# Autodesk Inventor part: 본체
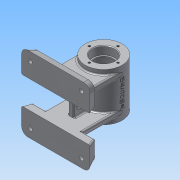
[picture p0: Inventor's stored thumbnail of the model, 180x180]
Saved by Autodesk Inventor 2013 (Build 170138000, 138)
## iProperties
Created: 2016-07
Part Number: 본체
Material: 알루미늄 6061
Document SubType Name: Modeling
Designer: Administrator
Density: 2.71 g/cm^3
Mass: 504.06 g
Surface Area: 540.608 cm^2
Volume: 186 cm^3
Author: Administrator
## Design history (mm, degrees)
sketch "스케치1"
  geometry: C1 r 27 at (0, 0); 1 further point
  constraints: 1 centre point, 1 coincident
  dimensions: "d0" = 54 diameter of C1
extrude "돌출1" new body sketch "스케치1" distance "d1" = 35; taper "d2" = 0 deg
sketch "스케치2"
  geometry: C1 r 27 at (0, 0) reference; C2 r 16 at (0, 0)
  constraints: 1 centre point, 1 coincident
  dimensions: "d3" = 32 diameter of C2
extrude "돌출2" cut sketch "스케치2" distance "d4" = 12; taper "d5" = 0 deg
chamfer "모따기1" distance "d6" = 1; stored, may be unused: second distance "d7" = 2, angle "d8" = 45 deg
fillet "모깎기1" dims "d9" = 0.3
sketch "스케치3"
  geometry: C1 r 15.7 at (0, 0) reference; C2 r 14 at (0, 0)
  constraints: 1 centre point, 1 coincident
  dimensions: "d10" = 28 diameter of C2
extrude "돌출3" cut sketch "스케치3" distance "d11" = 2; taper "d12" = 0 deg
sketch "스케치4"
  geometry: C1 r 27 at (0, 0) reference; C2 r 22 at (0, 0)
  constraints: 1 centre point, 1 coincident
  dimensions: "d13" = 44 diameter of C2
extrude "돌출4" cut sketch "스케치4" distance "d14" = 21; taper "d15" = 0 deg
fillet "모깎기2" dims "d16" = 3
sketch "스케치5"
  geometry: C1 r 27 at (0, 0) reference; 1 further point
  constraints: 1 vertical alignment
  dimensions: "d17" = 21 distance of C1.centre point (0, 21)
hole "구멍1" sketch "스케치5" at (0, 21) diameter "d18" = 3.242; stored, may be unused: countersink angle "d22" = 90 deg, drill point angle "d24" = 118 deg; dims "d19" = 8, "d20" = 4, "d21" = 2, "d23" = 10
node "작업 평면1"
sketch "스케치6"
  geometry: L1 (27, 35)-(-27, 35) reference; C1 r 5 at (0, 13); 2 further points
  constraints: 1 centre point, 1 midpoint, 1 vertical alignment
  dimensions: "d29" = 10 diameter of C1; "d30" = 22 distance from line of C1.centre L1
extrude "돌출5" join sketch "스케치6" stored distance "d31" = 21; taper "d32" = 0 deg
fillet "모깎기3" dims "d33" = 2
sketch "스케치7"
  geometry: C1 r 5 at (0, 0) reference; 2 further points
  constraints: 1 coincident
hole "구멍2" sketch "스케치7" at (0, 0) diameter "d34" = 5.188; stored, may be unused: countersink angle "d38" = 90 deg, drill point angle "d40" = 118 deg; dims "d35" = 8, "d36" = 4, "d37" = 2, "d39" = 10
node "작업 평면2"
sketch "스케치8"
  geometry: L1 (50, 20)-(-50, 20); L2 (-50, 20)-(-50, 55); L3 (-50, 55)-(50, 55); L4 (50, 55)-(50, 20); L5 (50, 20)-(-50, 55); L6 (-50, 20)-(50, 55); 3 further points
  constraints: 12 end point, 3 midpoint, 2 parallel, 1 horizontal, 1 perpendicular, 1 vertical alignment
  dimensions: "d42" = 100 distance of L2.end L3.end; "d43" = 35 distance of L1.end L2.end; "d44" = 55 vertical distance of L2.end point (0, 0)
extrude "돌출6" join sketch "스케치8" distance "d45" = 12; taper "d46" = 0 deg
sketch "스케치12"
  geometry: L1 (50, -20)-(-50, -20) reference; L2 (-50, -55)-(-50, -20) reference; L3 (-50, -20)-(50, -20) reference; L4 (50, -20)-(50, -55) reference; L5 (-27, -20)-(27, -20); L6 (27, -20)-(27, -28); L7 (27, -28)-(-27, -28); L8 (-27, -28)-(-27, -20); L9 (-27, -20)-(27, -28); L10 (27, -20)-(-27, -28); L11 (50, -55)-(-50, -55) reference; 3 further points
  constraints: 12 end point, 4 midpoint, 2 parallel, 1 horizontal, 1 perpendicular
  dimensions: "d65" = 54 distance of L6.end L7.end; "d66" = 8 distance of L5.end L6.end
extrude "돌출8" join sketch "스케치12" stored distance "d67" = 12; taper "d68" = 0 deg
fillet "모깎기6" dims "d69" = 2
fillet "모깎기9" dims "d72" = 2
node "작업 평면3"
sketch "스케치19"
  geometry: L1 (-57.621, 20)-(-70, 20) reference; L2 (-70, 20)-(-70, 55) reference; L3 (-58, 55)-(-58, 29.464) reference; L4 (-56, 26)-(-56, 22) reference; L5 (-56, 26)-(0, 26) reference; L6 (0, 26)-(0, 35) reference; L7 (-56, 22)-(0, 22) reference; L8 (0, -35)-(0, 22) reference; L9 (0, 22)-(0, 26) reference; L10 (27, 35)-(-27, 35) reference; L11 (-70, 55)-(-58, 55) reference; 2 further points
  constraints: 1 coincident, 3 other
  dimensions: "d130" = 35 distance from line of L10 point (0, 0); "d188" = 27 horizontal distance of L10.start point (0, 0) (derived)
feature "엠보싱1" sketch "스케치19" dims "d131" = 0.5, "d132" = 0
node "작업 평면4"
sketch "스케치21"
  geometry: C1 r 6 at (0, 0); 1 further point
  constraints: 1 centre point, 1 coincident
  dimensions: "d136" = 12 diameter of C1
extrude "돌출11" join sketch "스케치21" stored distance "d137" = 12; taper "d138" = 0 deg
fillet "모깎기18" dims "d139" = 2
sketch "스케치22"
  geometry: C1 r 6 at (0, 0) reference; 1 further point
  constraints: 1 coincident
hole "구멍6" sketch "스케치22" at (0, 0) diameter "d140" = 5.134; stored, may be unused: countersink angle "d144" = 90 deg, drill point angle "d146" = 0 deg; dims "d141" = 6, "d142" = 10, "d143" = 4, "d145" = 10
fillet "모깎기23" dims "d171" = 2
sketch "스케치26"
  geometry: L1 (16, 23.3)-(16, 34) reference; L2 (16, 34)-(17, 35) reference; L3 (17, 35)-(19.379, 35) reference; L4 (19.379, 35)-(19.379, 25) reference; L5 (19.379, 25)-(21, 24.026) reference; L6 (21, 24.026)-(22.621, 25) reference; L7 (22.621, 25)-(22.621, 35) reference; L8 (22.621, 35)-(27, 35) reference; L9 (27, 35)-(27, 20) reference; L10 (29, 18)-(30, 18) reference; L11 (30, 18)-(30, 15.594) reference; L12 (30, 15.594)-(22, 15.594) reference; L13 (22, 15.594)-(22, 18) reference; L14 (19, 21)-(14, 21) reference; L15 (14, 21)-(14, 23) reference; L16 (14, 23)-(15.7, 23) reference; L17 (15.7, -23)-(14, -23) reference; L18 (14, -23)-(14, -21) reference; L19 (14, -21)-(19, -21) reference; L20 (22, -18)-(22, 10.406) reference; L21 (22, 10.406)-(30, 10.406) reference; L22 (30, 10.406)-(30, 8) reference; L23 (30, 8)-(29, 8) reference; L24 (27, 6)-(27, -35) reference; L25 (27, -35)-(22.621, -35) reference; L26 (22.621, -35)-(22.621, -25) reference; L27 (22.621, -25)-(21, -24.026) reference; L28 (21, -24.026)-(19.379, -25) reference; L29 (19.379, -25)-(19.379, -35) reference; L30 (19.379, -35)-(17, -35) reference; L31 (17, -35)-(16, -34) reference; L32 (16, -34)-(16, -23.3) reference; L33 (-16, -23.3)-(-16, -34) reference; L34 (-16, -34)-(-17, -35) reference; L35 (-17, -35)-(-19.379, -35) reference; L36 (-19.379, -35)-(-19.379, -25) reference; L37 (-19.379, -25)-(-21, -24.026) reference; L38 (-21, -24.026)-(-22.621, -25) reference; L39 (-22.621, -25)-(-22.621, -35) reference; L40 (-22.621, -35)-(-27, -35) reference; L41 (-27, -35)-(-27, -28) reference; L42 (-58, -55)-(-70, -55) reference; L43 (-70, -55)-(-70, -20) reference; L44 (-70, -20)-(-27, -20) reference; L45 (-27, -20)-(-27, 18) reference; L46 (-29, 20)-(-70, 20) reference; L47 (-70, 20)-(-70, 55) reference; L48 (-70, 55)-(-58, 55) reference; L49 (-58, 55)-(-58, 30) reference; L50 (-56, 28)-(-29, 28) reference; L51 (-27, 30)-(-27, 35) reference; L52 (-27, 35)-(-22.621, 35) reference; L53 (-22.621, 35)-(-22.621, 25) reference; L54 (-22.621, 25)-(-21, 24.026) reference; L55 (-21, 24.026)-(-19.379, 25) reference; L56 (-19.379, 25)-(-19.379, 35) reference; L57 (-19.379, 35)-(-17, 35) reference; L58 (-17, 35)-(-16, 34) reference; L59 (-16, 34)-(-16, 23.3) reference; L60 (-15.7, 23)-(-14, 23) reference; L61 (-14, 23)-(-14, 21) reference; L62 (-14, 21)-(-19, 21) reference; L63 (-22, 18)-(-22, -18) reference; L64 (-19, -21)-(-14, -21) reference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; A1 r 3 centre (19, 18) between (22, 18) and (19, 21) reference; A2 r 0.3 centre (15.7, 23.3) between (15.7, 23) and (16, 23.3) reference; A3 r 0.3 centre (15.7, -23.3) between (16, -23.3) and (15.7, -23) reference; A4 r 3 centre (19, -18) between (19, -21) and (22, -18) reference; A5 r 0.3 centre (-15.7, -23.3) between (-15.7, -23) and (-16, -23.3) reference; A6 r 2 centre (-29, 18) between (-27, 18) and (-29, 20) reference; A7 r 2 centre (-56, 30) between (-58, 30) and (-56, 28) reference; A8 r 2 centre (-29, 30) between (-29, 28) and (-27, 30) reference; A9 r 0.3 centre (-15.7, 23.3) between (-16, 23.3) and (-15.7, 23) reference; A10 r 3 centre (-19, 18) between (-19, 21) and (-22, 18) reference; A11 r 3 centre (-19, -18) between (-22, -18) and (-19, -21) reference; 1 further point
  constraints: 2 end point, 1 perpendicular, 2 other
  dimensions: "d173" = 21 horizontal distance of L67.start L51.end
feature "리브3" sketch "스케치26" dims "d174" = 1, "d175" = 8, "d176" = 0, "d177" = 0, "d178" = 1, "d179" = 1
fillet "모깎기25" dims "d187" = 2
fillet "모깎기27" dims "d190" = 2
sketch "스케치32"
  geometry: L1 (35, 0)-(0, 0) reference; L2 (35, 10)-(35, 0) reference; L3 (35, 0)-(0, 0) reference; L4 (0, 0)-(0, 12) reference; L5 (0, 12)-(33, 12) reference; L6 (75, 0)-(75, 12) reference; L7 (75, 12)-(110, 12) reference; L8 (110, 12)-(110, 0) reference; L9 (110, 0)-(75, 0) reference; L10 (35, 10)-(35, 0) reference; L11 (35, 0)-(0, 0) reference; L12 (0, 0)-(0, 12) reference; L13 (0, 12)-(33, 12) reference; L14 (75, 0)-(75, 12) reference; L15 (75, 12)-(110, 12) reference; L16 (110, 12)-(110, 0) reference; L17 (110, 0)-(75, 0) reference; L18 (110, 0)-(105.632, 12); L19 (0, 0)-(4.368, 12); A1 r 2 centre (33, 10) between (35, 10) and (33, 12) reference; A2 r 2 centre (33, 10) between (35, 10) and (33, 12) reference; 1 further point
  constraints: 4 end point, 2 point on line
  dimensions: "d212" = 110 deg angle of L9 L18; "d214" = 110 deg angle of L1 L19
extrude "돌출16" cut sketch "스케치32" stored distance "d215" = 40; taper "d216" = 0 deg
node "작업 평면5"
sketch "스케치33"
  geometry: L1 (-100, 0)-(-100, 12) reference; L2 (0, 12)-(0, 0) reference; L3 (0, 0)-(-4.368, 12); L4 (-100, 0)-(0, 0) reference; L5 (-100, 12)-(0, 12) reference; L6 (-100, 0)-(-95.632, 12); 1 further point
  constraints: 4 end point, 2 point on line
  dimensions: "d219" = 110 deg angle of L4 L3; "d221" = 110 deg angle of L4 L6
extrude "돌출17" cut sketch "스케치33" distance "d222" = 40; taper "d223" = 0 deg
fillet "모깎기28" dims "d224" = 10
fillet "모깎기29" dims "d225" = 2
fillet "모깎기30" dims "d226" = 2
node "작업 평면6"
sketch "스케치34"
  geometry: L1 (-100, 12)-(0, 12) reference; L2 (0, 0)-(-100, 0) reference; L3 (-100, 0)-(-95.632, 12); L4 (0, 0)-(-4.368, 12); L5 (-100, 0)-(-100, 12) reference; L6 (0, 12)-(0, 0) reference; 1 further point
  constraints: 4 end point, 2 point on line
  dimensions: "d228" = 110 deg angle of L2 L4; "d229" = 110 deg angle of L2 L3
extrude "돌출18" cut sketch "스케치34" distance "d230" = 40; taper "d231" = 0 deg
sketch "스케치35"
  geometry: L1 (-21.111, -52)-(-21.111, -71.714) reference; L2 (-0.536, -50)-(50.536, -50) reference; L3 (69.232, -52)-(54, -52) reference; L4 (69.232, -71.714)-(69.232, -52) reference; L5 (-11.714, -79.232)-(61.714, -79.232) reference; L6 (-19.232, -52)-(-19.232, -71.714) reference; L7 (-4, -52)-(-19.232, -52) reference; L8 (-4, -52)-(-4, -56) reference; L9 (0, -60)-(50, -60) reference; L10 (54, -56)-(54, -52) reference; L11 (-4, -8)-(-4, -4) reference; L12 (0, 0)-(50, 0) reference; L13 (54, -4)-(54, -8) reference; L14 (50, -10)-(0, -10) reference; L15 (-20.632, -8)-(-4, -8) reference; L16 (-20.632, -8)-(-20.632, 20.632) reference; L17 (-20.632, 20.632)-(70.632, 20.632) reference; L18 (70.632, 20.632)-(70.632, -8) reference; L19 (54, -8)-(70.632, -8) reference; L20 (75, -75.603)-(75, -52) reference; L21 (-25, -52)-(-25, -75.603) reference; L22 (-15.603, -85)-(65.603, -85) reference; A1 r 4 centre (0, -56) between (-4, -56) and (0, -60) reference; A2 r 4 centre (50, -56) between (50, -60) and (54, -56) reference; A3 r 4 centre (0, -4) between (0, 0) and (-4, -4) reference; A4 r 4 centre (50, -4) between (54, -4) and (50, 0) reference; A5 r 2 centre (50, -8) between (50, -10) and (51, -9.732) reference; A6 r 2 centre (0, -8) between (-1, -9.732) and (0, -10) reference; 3 further points
  constraints: 1 horizontal alignment, 6 other
  dimensions: "d235" = 12.5 distance from line of L20 point (62.5, -72.5); "d236" = 12.5 distance from line of L21 point (-12.5, -72.5); "d237" = 12.5 distance from line of L22 point (-12.5, -72.5)
hole "구멍9" sketch "스케치35" at (-12.5, -72.5), (62.5, -72.5) diameter "d238" = 6; stored, may be unused: countersink angle "d242" = 90 deg, drill point angle "d244" = 0 deg; dims "d239" = 6, "d240" = 10, "d241" = 4, "d243" = 10
fillet "모깎기31" dims "d245" = 10
fillet "모깎기32" dims "d246" = 2
sketch "스케치36"
  geometry: C1 r 6 at (0, 0) reference; 1 further point
  constraints: 1 coincident
hole "구멍10" sketch "스케치36" at (0, 0) diameter "d247" = 5.188; stored, may be unused: countersink angle "d251" = 90 deg, drill point angle "d253" = 0 deg; dims "d248" = 6, "d249" = 10, "d250" = 4, "d252" = 10
sketch "스케치37"
  geometry: L1 (73, -24)-(63.603, -24) reference; L2 (26, 8)-(29.5, 8); L3 (10, 8)-(6.5, 8); L4 (10, 11.5)-(26, 11.5); L5 (10, 4.5)-(26, 4.5); L6 (40, -24)-(63.603, -24) reference; A1 r 3.5 centre (26, 8) between (29.5, 8) and (26, 11.5); A2 r 3.5 centre (10, 8) between (6.5, 8) and (10, 11.5); 1 further point
  constraints: 8 end point, 6 point on circle, 3 tangent, 2 centre point, 2 parallel, 1 collinear, 1 horizontal alignment
  dimensions: "d254" = 7 diameter of A1; "d255" = 7 diameter of A2; "d257" = 11.5 horizontal distance of L3.end point (18, 46); "d258" = 23 distance of L2.end L3.end; "d259" = 32 distance from line of L6 L2.end
extrude "돌출19" cut sketch "스케치37" distance "d260" = 40; taper "d261" = 0 deg
fillet "모깎기33" dims "d262" = 2
sketch "스케치38"
  geometry: L1 (-0.536, -50)-(50.536, -50) reference; L2 (69.232, -52)-(54, -52) reference; L3 (69.232, -71.714)-(69.232, -52) reference; L4 (-19.232, -52)-(-19.232, -71.714) reference; L5 (-4, -52)-(-19.232, -52) reference; L6 (-4, -52)-(-4, -56) reference; L7 (0, -60)-(50, -60) reference; L8 (54, -56)-(54, -52) reference; L9 (-4, -8)-(-4, -4) reference; L10 (0, 0)-(50, 0) reference; L11 (54, -4)-(54, -8) reference; L12 (50, -10)-(0, -10) reference; L13 (-19.232, -8)-(-4, -8) reference; L14 (-19.232, 11.714)-(-19.232, -8) reference; L15 (61.714, 19.232)-(-11.714, 19.232) reference; L16 (69.232, -8)-(69.232, 11.714) reference; L17 (54, -8)-(69.232, -8) reference; L18 (-25, -8)-(-25, 15.603) reference; L19 (-15.603, 25)-(65.603, 25) reference; L20 (75, 15.603)-(75, -8) reference; L21 (-11.714, -79.232)-(61.714, -79.232) reference; C1 r 5 at (62.5, -72.5) reference; C2 r 5 at (-12.5, -72.5) reference; A1 r 4 centre (0, -56) between (-4, -56) and (0, -60) reference; A2 r 4 centre (50, -56) between (50, -60) and (54, -56) reference; A3 r 4 centre (0, -4) between (0, 0) and (-4, -4) reference; A4 r 4 centre (50, -4) between (54, -4) and (50, 0) reference; A5 r 2 centre (50, -8) between (50, -10) and (51, -9.732) reference; A6 r 2 centre (0, -8) between (-1, -9.732) and (0, -10) reference; 5 further points
  constraints: 8 other
  dimensions: "d263" = 12.5 distance from line of L18 point (-12.5, 12.5); "d264" = 12.5 distance from line of L19 point (-12.5, 12.5); "d265" = 12.5 distance from line of L19 point (62.5, 12.5); "d266" = 12.5 distance from line of L20 point (62.5, 12.5)
hole "구멍11" sketch "스케치38" at (-12.5, 12.5), (62.5, 12.5) diameter "d267" = 6; stored, may be unused: countersink angle "d271" = 90 deg, drill point angle "d273" = 0 deg; dims "d268" = 6, "d269" = 10, "d270" = 4, "d272" = 10
node "솔리드1"
pattern_circular "원형 패턴1" dims angle "d26" = 360 deg
mirror "대칭1"
mirror "대칭6"
mirror "대칭7"
node "절단 모서리 투영1"
node "절단 모서리 투영5"
node "절단 모서리 투영9"
node "절단 모서리 투영13"
node "절단 모서리 투영14"
node "절단 모서리 투영15"
node "절단 모서리 투영16"
other parameters: "d129" = 27, "d217" = -35, "d227" = -35
